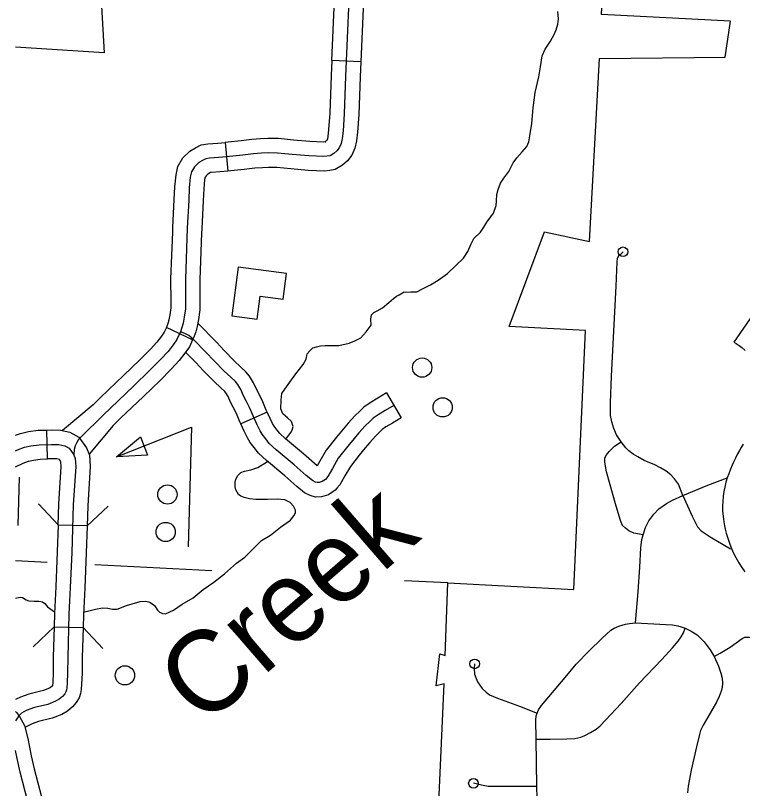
# Model space of a CAD drawing. Extents: x 653372 to 905732, y 627442 to 787275.
# Drawn here: x 654512 to 658285, y 758749 to 762760 of the extents above; entities that cross this region are included whole.
import ezdxf

# ---------------------------------------------------------------- set-up
doc = ezdxf.new("R2010")
doc.units = 0
for name, color, linetype in [('22', 7, 'Continuous'), ('31', 7, 'Continuous'), ('33', 7, 'Continuous'), ('35', 7, 'Continuous'), ('38', 7, 'Continuous'), ('45', 7, 'Continuous'), ('5', 7, 'Continuous'), ('56', 7, 'Continuous'), ('58', 7, 'Continuous'), ('6', 7, 'Continuous')]:
    doc.layers.add(name, color=color, linetype=linetype)

msp = doc.modelspace()

# ---------------------------------------------------------------- linework, layer by layer
at = {"layer": '22'}
for points in [[(658420.9, 761327.9), (658239.9, 761065.5), (658252, 761057.8), (658266.5, 761047.7), (658280.1, 761037.4), (658298.2, 761022.4)], [(658288.3, 760535.5), (658278, 760519), (658268.8, 760503.6), (658258.5, 760485.2), (658247.4, 760463.7), (658237.3, 760442.6), (658230.4, 760426.9), (658222.1, 760406.8), (658212.9, 760382.1), (658205.6, 760361.6), (658198.7, 760339.2), (658192.1, 760313.1), (658187.5, 760289.8), (658184, 760265.5), (658181.6, 760239), (658180.7, 760214), (658181.1, 760189.5), (658183.2, 760160.7), (658186.9, 760133.4), (658190.7, 760112.6), (658194.9, 760094.5), (658200.2, 760073.9), (658207.4, 760048.2), (658217.9, 760017), (658227.1, 759994.1), (658237.8, 759970.4), (658249.6, 759947.1), (658265.1, 759920.4), (658281.2, 759895.7), (658296.9, 759874.2)]]:
    msp.add_lwpolyline(points, dxfattribs=at)
at = {"layer": '31'}
for p, q in [((656303.3, 762519), (656153.4, 762525.6)), ((655599.8, 762101.3), (655613.6, 761951.9)), ((655431, 761076.6), (655295.7, 761141.4)), ((654678.5, 760459.1), (654674.2, 760609)), ((654883.1, 760112.4), (654733.2, 760116.3)), ((654712.3, 759588.1), (654862.2, 759584.2))]:
    msp.add_line(p, q, dxfattribs=at)
for points in [[(656153.4, 762525.6), (656167.5, 762842.2), (656177.9, 763053.4)], [(656327.8, 763046), (656317.3, 762835.1), (656303.3, 762519)], [(656242.4, 762838.7), (656224.9, 762444.7), (656218.1, 762249.7), (656211.6, 762161.5), (656207.6, 762120.7), (656202, 762095.2), (656191.9, 762073.6), (656180, 762056.9), (656164.4, 762044.1), (656145, 762032.3), (656112.6, 762027.5), (656034.7, 762030.8), (655947.5, 762038.2), (655871.7, 762046.2), (655823.3, 762046.7), (655788.1, 762044.9), (655746.2, 762041.4), (655690.8, 762034.5), (655621.8, 762028), (655567.5, 762023), (655518, 762019.7), (655498.9, 762016.5), (655481.5, 762007.5), (655463.1, 761996.7), (655440.6, 761974.5), (655425.6, 761948.3), (655419, 761921), (655413.6, 761865.1), (655410.7, 761801.2), (655403.5, 761655.9), (655393.7, 761391.9), (655393.9, 761274), (655393.8, 761237.9), (655387.7, 761194.4), (655382.1, 761163.9), (655375.7, 761141.3), (655368.2, 761119.2), (655349.1, 761079.4), (655329.3, 761051.4), (655303.5, 761017), (655266.2, 760976.3), (655209.4, 760920), (655123.5, 760837.2), (654967, 760686.9), (654853.3, 760574.4), (654839, 760560.5), (654829.9, 760544), (654822, 760526.5), (654816.9, 760507.8), (654814, 760480.8)], [(656153.4, 762525.6), (656149.9, 762447.6), (656143.2, 762253.7), (656136.9, 762167.9), (656133.4, 762132.4), (656130.5, 762119.4), (656126.9, 762111.6), (656124.6, 762108.5), (656120.8, 762105.3), (656119.1, 762104.3), (656121.9, 762104.7)], [(656303.3, 762519), (656299.8, 762441.7), (656293, 762245.6), (656286.4, 762155), (656281.8, 762109), (656273.5, 762071), (656256.9, 762035.7), (656235.4, 762005.3), (656207.9, 761982.8), (656171, 761960.3), (656143.5, 761956.3)], [(656121.9, 762104.7), (656108.7, 762102.8), (656039.5, 762105.7), (655954.6, 762112.9), (655876.1, 762121.1), (655821.8, 762121.7), (655783.1, 762119.7), (655738.4, 762116), (655682.7, 762109.1), (655614.9, 762102.7), (655599.8, 762101.3)], [(655327.7, 761635.5), (655328.5, 761659.2), (655335.8, 761804.7), (655338.7, 761870.4), (655344.9, 761933.4), (655355.1, 761976.3), (655380.7, 762020.8), (655417.1, 762056.6), (655445.2, 762073.2), (655474.8, 762088.5), (655509.3, 762094.3), (655561.6, 762097.8), (655599.8, 762101.3)], [(656143.5, 761956.3), (656116.4, 761952.3), (656030, 761956), (655940.5, 761963.5), (655867.4, 761971.2), (655824.8, 761971.7), (655793.1, 761970.1), (655753.9, 761966.8), (655699, 761959.9), (655628.8, 761953.3), (655613.6, 761951.9)], [(655613.6, 761951.9), (655573.4, 761948.2), (655526.7, 761945.1), (655522.9, 761944.5), (655517.8, 761941.9), (655509.2, 761936.7), (655500.5, 761928.2), (655496, 761920.4), (655493.2, 761908.6), (655488.4, 761859.7), (655485.6, 761797.6), (655478.4, 761652.7), (655477.6, 761629.9)], [(655295.7, 761141.4), (655298.6, 761147.6), (655304, 761163.5), (655308.9, 761181), (655313.7, 761206.4), (655318.8, 761243.2), (655318.9, 761274.1), (655318.6, 761393.2), (655327.7, 761635.5)], [(655477.6, 761629.9), (655468.7, 761390.6), (655468.9, 761274), (655468.8, 761232.6), (655461.8, 761182.3), (655455.2, 761146.9), (655447.3, 761119.1), (655437.8, 761090.9), (655431, 761076.6)], [(655295.7, 761141.4), (655284.2, 761117.6), (655268.7, 761095.6), (655245.7, 761065), (655212.1, 761028.3), (655156.9, 760973.7), (655071.5, 760891.2), (654953.7, 760778.2)], [(655431, 761076.6), (655414, 761041.2), (655389.9, 761007.2), (655361.3, 760969.1), (655320.2, 760924.3), (655261.8, 760866.4), (655175.5, 760783.2), (655057.6, 760670)], [(654953.7, 760778.2), (654914.6, 760740.6), (654756.1, 760606.1)], [(655057.6, 760670), (655019.3, 760633.2), (654893.4, 760484.7)], [(654511.7, 760582.6), (654537, 760592), (654579, 760601.5), (654629.1, 760607.7), (654674.2, 760609)], [(654674.2, 760609), (654699.6, 760609.8), (654746.1, 760608.4), (654794, 760597.4), (654840.9, 760572.2), (654880.2, 760517.3), (654895.9, 760478.5), (654899.5, 760419.6), (654886.7, 760216.8), (654883.1, 760111.2)], [(654511.7, 760501.6), (654522.9, 760506.7), (654558.4, 760519.9), (654591.9, 760527.5), (654634.8, 760532.9), (654699.5, 760534.7), (654736.6, 760533.6), (654767.4, 760526.5), (654790, 760514.4), (654814, 760480.8), (654821.8, 760461.6), (654824.4, 760419.7), (654811.7, 760220.5), (654803.4, 759974.3), (654796, 759792), (654789, 759653.9), (654783.2, 759429.1), (654782.2, 759348.8), (654779.7, 759296.6), (654778.5, 759271.4), (654776.7, 759260.6), (654773.6, 759251.1), (654767.1, 759240.4), (654755.3, 759227.4), (654738.2, 759212.3), (654720.3, 759202.1), (654679, 759186.2), (654610.1, 759169.3), (654567.8, 759154.4), (654542.7, 759140.9), (654528.9, 759126.1), (654515, 759106.6), (654511.7, 759100.9)], [(654511.7, 760418.9), (654551.7, 760437.5), (654579.8, 760447.9), (654604.8, 760453.5), (654640.6, 760458), (654678.5, 760459.1)], [(654733.2, 760116.3), (654736.8, 760224.1), (654749.2, 760419.8), (654747.7, 760444.6), (654739.6, 760456), (654727, 760458.9), (654699.5, 760459.7), (654678.5, 760459.1)], [(654733.2, 760116.3), (654728.4, 759977.1), (654721.1, 759795.4), (654714.1, 759656.8), (654712.3, 759588.1)], [(654883.1, 760111.2), (654878.3, 759971.5), (654870.9, 759788.6), (654864, 759651), (654862.2, 759584.2)], [(654712.3, 759588.1), (654708.2, 759430.5), (654707.3, 759351.1), (654704.8, 759300.2), (654703.9, 759282.4), (654702.5, 759280.9), (654694.3, 759273.6), (654688.2, 759270.1), (654656.5, 759258), (654588.6, 759241.3), (654581.9, 759238.9)], [(654862.2, 759584.2), (654858.2, 759427.7), (654857.2, 759346.5), (654854.6, 759293), (654853.2, 759263.6), (654849.8, 759242.6), (654842.1, 759219.5), (654827.5, 759195.3), (654808.1, 759174), (654782.1, 759151), (654752.5, 759134.1), (654701.5, 759114.5), (654631.5, 759097.3), (654631.8, 759097.4)], [(654581.9, 759238.9), (654537.4, 759223.2), (654511.7, 759210.8)], [(654511.7, 759149.2), (654516.5, 759143.7), (654533.2, 759122.6), (654557.9, 759075.6), (654576.1, 759009.3), (654593.3, 758919.6), (654608.4, 758851.8), (654647.2, 758706), (654658.2, 758659.1)], [(654631.8, 759097.4), (654598.2, 759085.6), (654560.7, 759065.4)], [(654574.4, 758687.8), (654535.5, 758834), (654519.9, 758904.4), (654511.7, 758947)]]:
    msp.add_lwpolyline(points, dxfattribs=at)
at = {"layer": '33'}
for points in [[(657975.2, 760269.5), (657951.8, 760328.2), (657931.7, 760356.8), (657912.3, 760376.3), (657888.9, 760396), (657859.5, 760413.9), (657826, 760429.9), (657795.5, 760442.8), (657774.7, 760450.4), (657741.3, 760469.4), (657717.8, 760483.1), (657694.3, 760501.8), (657678.8, 760516.2), (657655, 760547.9), (657630.9, 760583.6), (657616.9, 760617), (657605.9, 760651.3), (657599.9, 760684.5), (657598.9, 760715.5), (657599.9, 760749.4), (657604.1, 760888.5), (657628.1, 761355.4), (657633.8, 761479.7), (657635.7, 761501.1), (657645.1, 761515.8), (657654.1, 761523.1), (657664.4, 761533.8)], [(657769.3, 760064.8), (657719.7, 760074.3), (657695, 760086.1), (657676.5, 760099.6), (657660.9, 760114.1), (657650.7, 760139.3), (657628, 760215), (657578.4, 760392.3), (657569.9, 760442.5), (657570.6, 760464.5), (657578.1, 760481.3), (657592.5, 760497.8), (657620.3, 760525), (657655, 760547.9)], [(657729, 759608.2), (657743.3, 759769.5), (657751.4, 759897.1), (657757.6, 759998.1), (657762.1, 760040.6), (657769.3, 760064.8), (657781, 760102.9), (657798, 760137.5), (657823.6, 760171.9), (657850, 760199.9), (657890.2, 760228.5), (657921.6, 760244.6), (657975.2, 760269.5), (658103.6, 760322.8), (658204.4, 760362)], [(657975.2, 760269.5), (658023.8, 760162.2), (658051.1, 760106.4), (658070.4, 760085.9), (658116.4, 760055.5), (658222.8, 759993)], [(657218.6, 758701.3), (657217.1, 758759.7), (657213.8, 759005.2), (657211.5, 759104.7), (657214.2, 759126.5), (657218.1, 759140.8), (657226.1, 759158.4), (657241.9, 759180.6), (657364.8, 759324.9), (657421, 759394.3), (657488.2, 759463.5), (657554.5, 759528), (657601.7, 759571.2), (657619.2, 759581.3), (657642.8, 759592.2), (657676.7, 759602.9), (657698.7, 759606.3), (657729, 759608.2)], [(657729, 759608.2), (657856.1, 759602.6), (657921, 759598), (657948, 759593.5), (657965.9, 759587.6), (657986.5, 759580.6), (658018.5, 759566.3), (658049.9, 759546.2), (658086.1, 759511), (658117.3, 759469.1), (658136.8, 759434.4), (658159.5, 759384.7), (658172.2, 759348.6), (658178.9, 759321.3), (658180.8, 759296.7), (658179, 759273.3), (658173, 759254.1), (658163.1, 759226.7), (658150, 759197.3), (658104, 759120.4), (658079.9, 759078.5), (658066.3, 759050.2), (658060.9, 759030.1), (658046.2, 758966.4), (658018.6, 758845.3), (658002.2, 758761.6), (657998.5, 758727.7)], [(657213.8, 759005.2), (657286.7, 759005.1), (657372.7, 759007), (657413.6, 759009.3), (657445.2, 759015.3), (657466.8, 759024.8), (657494.9, 759039.9), (657524.2, 759057.7), (657546.5, 759075.1), (657573.5, 759103.6), (657653.9, 759191.2), (657749.1, 759297), (657865.7, 759419.2), (657920.4, 759480.1), (657949.7, 759513.8), (657966.9, 759536.2), (657978.1, 759557.2), (657986.5, 759580.6)], [(658136.8, 759434.4), (658168.8, 759451.5), (658220.3, 759483.5), (658282.3, 759527.5), (658296.4, 759534), (658307.6, 759534.7), (658319.3, 759534.3), (658341.5, 759527.8), (658378.4, 759516), (658390.5, 759512), (658399, 759511.7), (658412.9, 759512.9), (658439.7, 759519), (658505.2, 759538.3), (658529.9, 759544.5), (658546.5, 759546.2), (658560.3, 759545.2), (658568.4, 759542.1)], [(656894.2, 759396.2), (656891.5, 759372.6), (656893.9, 759343), (656908.5, 759303.1), (656933.7, 759268.9), (656954.1, 759249.2), (656971.4, 759236.2), (657012.3, 759218.6), (657127.9, 759177), (657218.1, 759140.8)], [(657217.1, 758759.7), (657050.4, 758759.5), (656986.9, 758760.4), (656964.7, 758760.6), (656946.8, 758763.2), (656929.8, 758767.3), (656888.3, 758776.8)]]:
    msp.add_lwpolyline(points, dxfattribs=at)
for centre in [(657664.4, 761533.8), (656894.2, 759396.2), (656888.3, 758776.8)]:
    msp.add_circle(centre, 25, dxfattribs=at)
at = {"layer": '35'}
for points in [[(657235.4, 762493.9), (657244.3, 762551.1), (657260.8, 762585.7), (657288.8, 762626.1), (657307.4, 762661.6), (657317.4, 762686), (657325.5, 762714.7), (657329.4, 762742.4), (657325.4, 762779.6)], [(656798.7, 761464.8), (656836.6, 761501.4), (656858.4, 761535.7), (656875.7, 761574.9), (656890.7, 761602.8), (656924.7, 761635.3), (656941.6, 761662.2), (656958.4, 761688.2), (656991.9, 761734.4), (657005.4, 761773.7), (657007, 761796.4), (657009.9, 761830.3), (657016.4, 761857.5), (657028.7, 761890.2), (657045.6, 761916.2), (657072.1, 761950.3), (657082.2, 761970.8), (657094.2, 761995), (657112.6, 762021.3), (657140.9, 762052.6), (657165.3, 762079.3), (657175.5, 762104.5), (657181.2, 762134.5), (657191.6, 762199.4), (657197.8, 762280.5), (657208.7, 762360.5), (657228.2, 762442.1), (657235.4, 762493.9)], [(655915.5, 760561.9), (655940.1, 760596.1), (655948.1, 760608.2), (655952.4, 760626.9), (655943.7, 760652.7), (655923.6, 760673.1), (655899.6, 760692.8), (655889.1, 760719.5), (655890.4, 760764.9), (655893.3, 760797.9), (655909.1, 760821.9), (655935.7, 760858), (655967.3, 760901.5), (656004.6, 760949.5), (656019.6, 760977.4), (656026.1, 761003.7), (656038.8, 761020.3), (656054.4, 761034.9), (656073.5, 761041), (656094.4, 761046), (656118.5, 761047.2), (656189.4, 761047.9), (656243.6, 761059.5), (656273.3, 761071.8), (656303.9, 761087), (656331.3, 761118.3), (656356.9, 761153.4), (656355, 761183.7), (656359.5, 761206.3), (656371.2, 761219.2), (656389.4, 761227.1), (656416.3, 761243.3), (656449.3, 761270.7), (656473.5, 761290.7), (656489, 761303.5), (656502.2, 761311.1), (656528.1, 761325.5), (656536.6, 761324.3), (656563, 761325.4), (656595.2, 761326.3), (656624, 761341.5), (656665.3, 761362.9), (656704.7, 761386.3), (656753.9, 761420.8), (656798.7, 761464.8)], [(654864.6, 759664.3), (654926.9, 759680.1), (654963, 759686.6), (654991.2, 759684.8), (655014.7, 759679.3), (655039.3, 759680.5), (655088, 759698.9), (655159.5, 759720.4), (655188.8, 759721.4), (655209.5, 759716), (655233.5, 759698.3), (655247.9, 759674.2), (655259.9, 759664.4), (655263.6, 759662.4), (655274.8, 759657.4), (655289.8, 759656), (655331, 759674.6), (655377.3, 759705.3), (655433.1, 759739.5), (655485.4, 759782.4), (655541.8, 759819.4), (655596, 759863.2), (655658.1, 759918), (655701.5, 759948.8), (655740.5, 759987.4), (655789.2, 760036), (655834.4, 760063.9), (655887.6, 760104.8), (655938.8, 760141.5), (655956.4, 760163.6), (655964.5, 760180.4), (655964.9, 760193.6), (655954.2, 760214.7), (655936.8, 760233.2), (655908.9, 760247.3), (655869.3, 760250.4), (655820.1, 760249), (655759.6, 760248), (655725.8, 760252.8), (655697.6, 760259.3), (655680.8, 760266.4), (655668.8, 760275.3), (655654.4, 760299.3), (655651.1, 760314.6), (655650.9, 760338.2), (655655.2, 760355.1), (655665.2, 760373.7), (655680.7, 760388.3), (655699.8, 760395.3), (655733.1, 760401.9), (655769.4, 760414), (655819.9, 760446.3)], [(654511.7, 759736.7), (654519.3, 759738.9), (654535.6, 759742), (654547.6, 759740.9), (654566.9, 759729.1), (654580.8, 759723), (654609, 759721.5), (654632.9, 759721.4), (654651.8, 759718.1), (654663.5, 759708.5), (654678.5, 759691.2), (654714.6, 759666.3)]]:
    msp.add_lwpolyline(points, dxfattribs=at)
at = {"layer": '38'}
for points in [[(654733.2, 760116.9), (654630.8, 760226.5)], [(654992.7, 760214.2), (654883.1, 760111.8)], [(654603.5, 759484.8), (654712.3, 759588.1)], [(654862.2, 759584.2), (654965.5, 759475.5)]]:
    msp.add_lwpolyline(points, dxfattribs=at)
at = {"layer": '45'}
for p, q in [((656437.8, 760801.3), (656513.7, 760672)), ((655817.6, 760702.6), (655680.5, 760641.7))]:
    msp.add_line(p, q, dxfattribs=at)
for points in [[(655817.6, 760702.6), (655813.2, 760712.4), (655794.6, 760756), (655776.4, 760794.4), (655763.1, 760820.3), (655747.4, 760853.9), (655726.5, 760888.7), (655707.6, 760911.6), (655680.3, 760937.4), (655647.2, 760968.1), (655594.6, 761021.8), (655556.3, 761063.4), (655458.1, 761162.8)], [(656475.7, 760736.7), (656430.5, 760710.1), (656393.5, 760688.2), (656367.7, 760669.9), (656349.9, 760653.1), (656326.6, 760630.3), (656294, 760594.9), (656268.7, 760565.9), (656235.9, 760525.5), (656187, 760462.7), (656156.6, 760409.5), (656133.2, 760368.9), (656119.9, 760353.3), (656103.1, 760341.4), (656087.9, 760337), (656076.8, 760336.4), (656068, 760338.9), (656053.1, 760346.5), (656020.7, 760373.6), (655958, 760428.7), (655864.3, 760507), (655828, 760539.6), (655810.1, 760563.2), (655792.2, 760587.2), (655780.8, 760605.7), (655765.2, 760635.7), (655744.5, 760682.5), (655726.2, 760725.2), (655709.1, 760761.2), (655695.7, 760787.3), (655681.2, 760818.6), (655665.1, 760845.2), (655652.7, 760860.3), (655629, 760882.7), (655594.9, 760914.3), (655540.2, 760970.1), (655502, 761011.6), (655433.1, 761081.3), (655411.9, 761098.8), (655390.1, 761109.7), (655368.2, 761119.2)], [(655680.5, 760641.7), (655675.7, 760652.5), (655657.9, 760694.3), (655641.9, 760728), (655628.4, 760754.3), (655614.9, 760783.3), (655603.7, 760801.8), (655597.8, 760808.9), (655577.7, 760828), (655542.6, 760860.6), (655485.8, 760918.4), (655447.7, 760959.9), (655394.6, 761013.6)], [(656437.8, 760801.3), (656392.4, 760774.7), (656352.6, 760751.1), (656320, 760728), (656297.9, 760707.2), (656272.7, 760682.5), (656238.1, 760644.9), (656211.4, 760614.2), (656177.2, 760572.2), (656124.5, 760504.5), (656091.5, 760446.8), (656077.9, 760423.2)], [(656077.9, 760423.2), (656006.8, 760485.7), (655913.4, 760563.7), (655883.4, 760590.6), (655870, 760608.2), (655854.3, 760629.4), (655846.1, 760642.7), (655832.9, 760668.2), (655817.6, 760702.6)], [(656513.7, 760672), (656468.6, 760645.5), (656434.4, 760625.2), (656415.3, 760611.7), (656401.8, 760599), (656380.4, 760578.1), (656349.9, 760544.8), (656326.1, 760517.6), (656294.6, 760478.8), (656249.5, 760420.8), (656221.6, 760372.1), (656194.7, 760325.4), (656178.8, 760306.9)], [(656178.8, 760306.9), (656170.8, 760297.5), (656136.2, 760272.9), (656100.4, 760262.5), (656068.2, 760260.9), (656040.6, 760268.7), (656011.6, 760283.5), (655971.8, 760316.7), (655909.2, 760371.8), (655815.2, 760450.3), (655772.6, 760488.5), (655750.1, 760518.1), (655730, 760545.1), (655715.4, 760568.8), (655697.6, 760603.2), (655680.5, 760641.7)]]:
    msp.add_lwpolyline(points, dxfattribs=at)
at = {"layer": '5'}
for points in [[(654676.2, 759922.4), (654511.7, 759930.9)], [(655529.9, 759878.6), (654922.7, 759909.8)], [(656754.5, 759815.7), (656530.5, 759827.2)]]:
    msp.add_lwpolyline(points, dxfattribs=at)
at = {"layer": '56'}
for p, q in [((655036.6, 760470.2), (655160.3, 760573.8)), ((655160.3, 760573.8), (655197.7, 760478.9)), ((655197.7, 760478.9), (655036.6, 760470.2))]:
    msp.add_line(p, q, dxfattribs=at)
for points in [[(655036.6, 760470.2), (655425.8, 760623.6), (655407.2, 760002.9)], [(654531.7, 760365), (654524.1, 760113.3)]]:
    msp.add_lwpolyline(points, dxfattribs=at)
for centre in [(656622.2, 760933), (656728.4, 760726.8), (655300.3, 760274.8), (655291.1, 760080.3), (655079.7, 759336.6)]:
    msp.add_circle(centre, 50, dxfattribs=at)
at = {"layer": '58'}
msp.add_lwpolyline([(655666.8, 761454.1), (655633.7, 761202.3), (655766.6, 761184.8), (655782.2, 761304), (655901.2, 761288.4), (655918.6, 761421)], close=True, dxfattribs=at)
at = {"layer": '6'}
for points in [[(656702.3, 758523.5), (656736.5, 759292.7), (656693.9, 759281.6), (656713.9, 759448), (656741.7, 759439.9), (656754.5, 759815.7), (657408.7, 759782.1), (657469, 761126), (657073.7, 761145.7), (657257, 761638), (657490.9, 761587.3), (657542.4, 762537.2), (658194.6, 762543.4), (658222.8, 762730.3), (657552.4, 762765.5), (657660.1, 765070.5), (656796, 765115.8)], [(656278.9, 763577.1), (656026.4, 763582.8), (656002.1, 763576.5), (655826.1, 763850.2), (655829.8, 763844), (654634.2, 763901.6), (654658.3, 763811.8), (654680.9, 763744), (654711, 763665.1), (654718.8, 763502.9), (654728.9, 763422.5), (654730.7, 763325.3), (654760.5, 763258.2), (654823.1, 763193.5), (654867.2, 763153.8), (654879.8, 763140.6), (654941.3, 763112.2), (654972.3, 762566.2), (654511.7, 762595.3)]]:
    msp.add_lwpolyline(points, dxfattribs=at)

# ---------------------------------------------------------------- texts
at = {"layer": '35'}
msp.add_text('Creek', height=422.4, rotation=40.9103, dxfattribs=at).set_placement((655485.9, 759061))

doc.saveas('drawing.dxf')
